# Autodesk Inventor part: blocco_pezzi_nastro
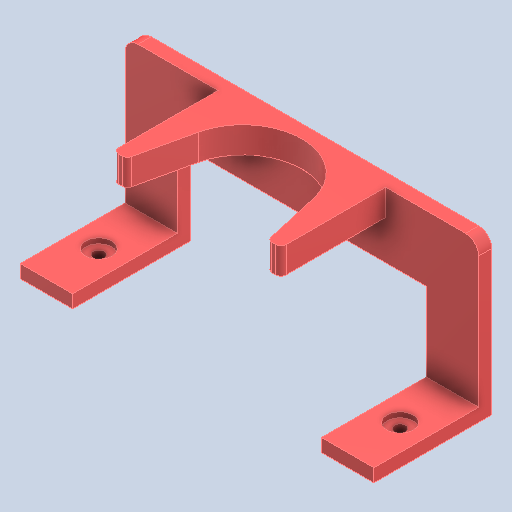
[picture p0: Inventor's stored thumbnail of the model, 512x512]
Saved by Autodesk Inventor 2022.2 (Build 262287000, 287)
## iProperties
Created: 2024-10
Part Number: blocco_pezzi_nastro
Material: Alluminio 6061
Document SubType Name: Modeling
Designer: 18907419
Density: 2.7 g/cm^3
Appearance: Default
Author: 18907419
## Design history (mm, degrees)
feature "Solido1"
node "Solido2"
